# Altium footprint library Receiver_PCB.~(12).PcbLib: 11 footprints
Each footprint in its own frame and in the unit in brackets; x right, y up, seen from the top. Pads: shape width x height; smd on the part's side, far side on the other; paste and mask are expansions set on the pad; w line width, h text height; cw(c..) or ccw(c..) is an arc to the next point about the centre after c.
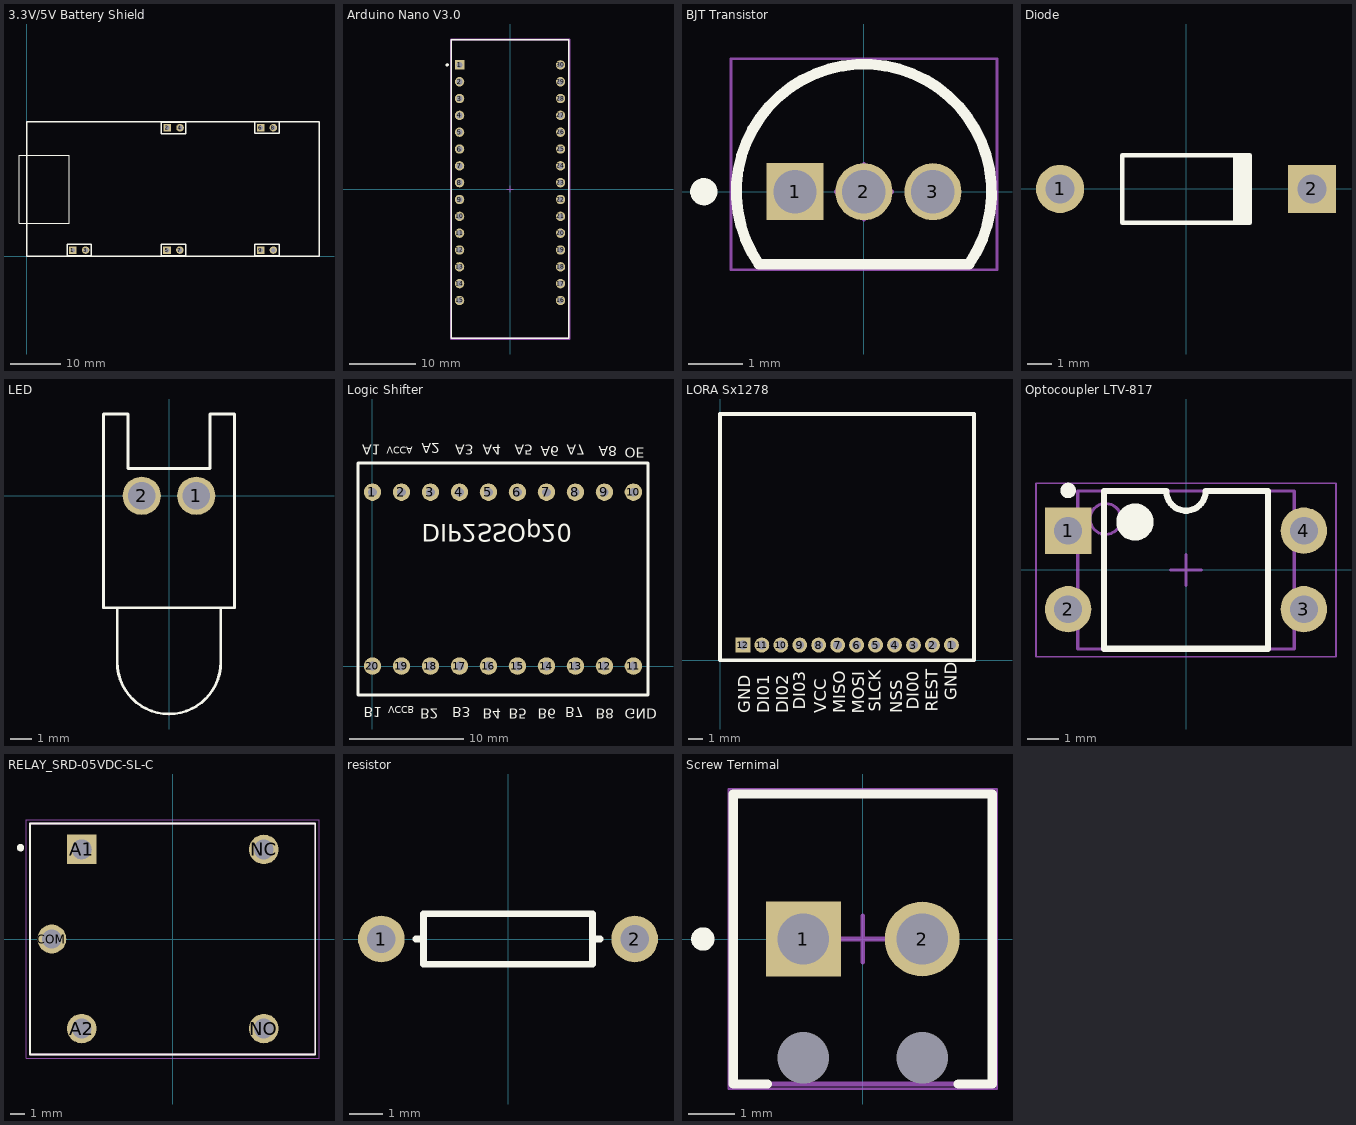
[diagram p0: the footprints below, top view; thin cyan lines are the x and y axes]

## 3.3V/5V Battery Shield [mm]
pads (10):
  rect 1.5x1.5 hole 0.9: 1(9.144,1.27) 2(27.853,25.518) 5(27.813,1.27) 6(46.355,25.527) 9(46.355,1.27)
  round 1.5 hole 0.9: 3(11.684,1.27) 4(30.393,25.518) 7(30.353,1.27) 8(48.895,25.527) 11(48.895,1.27)
Top Overlay:
  lines w0.127: -1.524,6.604 8.476,6.604 8.476,20.104 -1.524,20.104 -1.524,6.604
  lines w0.254: 0,0 57.935,0 57.935,26.753 0,26.753 0,0 ; 8.01,0.127 12.827,0.127 12.827,2.407 8.01,2.407 8.01,0.127 ; 26.679,0.127 31.496,0.127 31.496,2.407 26.679,2.407 26.679,0.127 ; 26.719,24.375 31.536,24.375 31.536,26.655 26.719,26.655 26.719,24.375 ; 45.221,0.127 50.038,0.127 50.038,2.407 45.221,2.407 45.221,0.127 ; 45.221,24.384 50.038,24.384 50.038,26.664 45.221,26.664 45.221,24.384

## Arduino Nano V3.0 [mil]
pads (30):
  rect 55.67x55.67 hole 35.98 paste-39370.1 mask+0: 1(-300,737.5)
  round 55.67 hole 35.98 paste-39370.1 mask+0: 2(-300,637.5) 3(-300,537.5) 4(-300,437.5) 5(-300,337.5) 6(-300,237.5) 7(-300,137.5) 8(-300,37.5) 9(-300,-62.5) 10(-300,-162.5) 11(-300,-262.5) 12(-300,-362.5) 13(-300,-462.5) 14(-300,-562.5) 15(-300,-662.5) 16(300,-662.5) 17(300,-562.5) 18(300,-462.5) 19(300,-362.5) 20(300,-262.5) 21(300,-162.5) 22(300,-62.5) 23(300,37.5) 24(300,137.5) 25(300,237.5) 26(300,337.5) 27(300,437.5) 28(300,537.5) 29(300,637.5) 30(300,737.5)
Top Overlay:
  circle w9.84: c-373.62,737.5 r4.92
  lines w7.87: -350,-887.5 -350,887.5 350,887.5 350,-887.5 -350,-887.5
Top 3D Body:
  lines w7.87: -350,-887.5 -350,887.5 350,887.5 350,-887.5 -350,-887.5
Top Courtyard:
  lines w7.87: -353.94,-891.44 -353.94,891.44 353.94,891.44 353.94,-891.44 -353.94,-891.44
Top Assembly:
  lines w7.87: -353.94,-891.44 -353.94,891.44 353.94,891.44 353.94,-891.44 -353.94,-891.44
Top Component Center:
  lines w3.94: -19.68,0 19.69,0 ; 0,-19.68 0,19.69
3D body "UNK_Arduino_A000005_eec.STEP": height 10, standoff 0, extent -353.94,-891.44 353.94,891.44

## BJT Transistor [mm]
pads (3):
  rect 1.05x1.05 hole 0.8: 1(-1.27,0)
  round 1.05 hole 0.8 paste+0: 2(0,0)
  round 1.05 hole 0.8: 3(1.27,0)
Top Overlay:
  circle w0.25: c-2.95,0 r0.125
  lines w0.2: -1.934,-1.335 cw(c0,0) 1.934,-1.335 -1.934,-1.335
Mechanical 13:
  lines w0.1: -1.934,-1.335 cw(c0,0) 1.934,-1.335 -1.934,-1.335
Mechanical 15:
  lines w0.05: -2.45,-1.435 2.45,-1.435 2.45,2.45 -2.45,2.45 -2.45,-1.435
  lines w0.1: -0.5,0 0.5,0 ; 0,-0.5 0,0.5
3D body: height 7.87, standoff 2.54, extent -2.349,-1.334 2.357,2.359

## Diode [mm]
pads (2):
  round 2 hole 1.2: 1(-5.23,0)
  rect 2x2 hole 1.2: 2(5.23,0)
Top Overlay:
  rectangle: 1.95,-1.401 2.75,1.399
  lines w0.2: 2.65,-1.4 -2.65,-1.4 -2.65,1.4 2.65,1.4

## LED [mil]
pads (2):
  round 70 hole 50: 1(50,0) 2(-50,0)
Top Overlay:
  lines w5: -95,-205 -95,-305 ccw(c0,-305) 95,-305 95,-205 ; -120,-205 -120,150 -75,150 -75,50 75,50 75,150 120,150 120,-205 -120,-205

## Logic Shifter [mil]
pads (20):
  round 60 hole 30: 1(0,600) 2(100,600) 3(200,600) 4(300,600) 5(400,600) 6(500,600) 7(600,600) 8(700,600) 9(800,600) 10(900,600) 11(900,0) 12(800,0) 13(700,0) 14(600,0) 15(500,0) 16(400,0) 17(300,0) 18(200,0) 19(100,0) 20(0,0)
Top Overlay:
  lines w10: -50,-100 950,-100 950,700 -50,700 -50,-100
  text "B1" at -30,-130 h60
  text "A8" at 780,770 h60
  text "A7" at 670,775 h60
  text "A6" at 580,770 h60
  text "A5" at 490,775 h60
  text "A4" at 380,775 h60
  text "A3" at 285,775 h60
  text "A2" at 170,780 h60
  text "A1" at -35,775 h60
  text "B3" at 275,-130.67 h60
  text "B4" at 380,-135 h60
  text "B5" at 470,-135.67 h60
  text "B6" at 570,-135.67 h60
  text "B7" at 665,-130 h60
  text "B8" at 770,-135.67 h60
  text "B2" at 165,-135 h60
  text "VCCA" at 50,765 h40
  text "OE" at 870,765 h60
  text "GND" at 870,-135.67 h60
  text "VCCB" at 55.04,-130.44 h40
  text "DIP2SSOp20" at 169.99,490 h60

## LORA Sx1278 [mm]
pads (12):
  round 1 hole 0.6: 1(15.494,1.016) 2(14.224,1.016) 3(12.954,1.016) 4(11.684,1.016) 5(10.414,1.016) 6(9.144,1.016) 7(7.874,1.016) 8(6.604,1.016) 9(5.334,1.016) 10(4.064,1.016) 11(2.794,1.016)
  rect 1x1 hole 0.6: 12(1.524,1.016)
Top Overlay:
  lines w0.254: 0,0 17,0 17,16.5 0,16.5 0,0
  text "GND" at 15.852,-2.664 h0.8
  text "REST" at 14.582,-3.463 h0.8
  text "DI00" at 13.312,-3.33 h0.8
  text "NSS" at 12.192,-3.556 h0.8
  text "SLCK" at 10.772,-3.463 h0.8
  text "MOSI" at 9.652,-3.601 h0.8
  text "MISO" at 8.382,-3.556 h0.8
  text "VCC" at 7.112,-3.556 h0.8
  text "DI03" at 5.692,-3.33 h0.8
  text "DI02" at 4.572,-3.556 h0.8
  text "GND" at 2.032,-3.556 h0.8
  text "DI01" at 3.302,-3.556 h0.8

## Optocoupler LTV-817 [mm]
pads (4):
  rect 1.5x1.5 hole 0.9: 1(-3.81,1.27)
  round 1.5 hole 0.9: 2(-3.81,-1.27) 3(3.81,-1.27) 4(3.81,1.27)
Top Overlay:
  circle w0.25: c-3.81,2.57 r0.125
  circle w0.6: c-1.65,1.55 r0.3
  lines w0.2: -2.65,-2.55 -2.65,2.55 -0.635,2.55 ccw(c0,2.55) 0.635,2.55 2.65,2.55 2.65,-2.55 -2.65,-2.55
Mechanical 13:
  circle w0.1: c-2.6,1.65 r0.5
  lines w0.1: -3.5,-2.55 -3.5,2.55 3.5,2.55 3.5,-2.55 -3.5,-2.55
Mechanical 15:
  lines w0.05: -4.85,-2.8 -4.85,2.8 4.85,2.8 4.85,-2.8 -4.85,-2.8
  lines w0.1: -0.5,0 0.5,0 ; 0,-0.5 0,0.5
3D body: height 2.37, standoff 0, extent -3.945,0.77 -3.675,1.77
3D body: height 2.64, standoff 2.37, extent -3.945,0.77 -3.5,1.77
3D body: height 0, standoff -1.6, extent -3.945,0.91 -3.675,1.63
3D body: height 2.37, standoff 0, extent -3.945,-1.77 -3.675,-0.77
3D body: height 2.64, standoff 2.37, extent -3.945,-1.77 -3.5,-0.77
3D body: height 0, standoff -1.6, extent -3.945,-1.63 -3.675,-0.91
3D body: height 2.37, standoff 0, extent 3.675,-1.77 3.945,-0.77
3D body: height 2.64, standoff 2.37, extent 3.5,-1.77 3.945,-0.77
3D body: height 0, standoff -1.6, extent 3.675,-1.63 3.945,-0.91
3D body: height 2.37, standoff 0, extent 3.675,0.77 3.945,1.77
3D body: height 2.64, standoff 2.37, extent 3.5,0.77 3.945,1.77
3D body: height 0, standoff -1.6, extent 3.675,0.91 3.945,1.63
3D body: height 4.5, standoff 0.5, extent -3.5,-2.55 3.5,2.55

## RELAY_SRD-05VDC-SL-C [mm]
pads (5):
  rect 1.98x1.98 hole 1.32 paste+0: A1(-6.1,6)
  round 1.98 hole 1.32: A2(-6.1,-6) NC(6.1,6) NO(6.1,-6)
  round 1.935 hole 1.29: COM(-8.1,0)
Top Overlay:
  circle w0.3: c-10.2,6.119 r0.1
  lines w0.127: -9.55,-7.75 9.55,-7.75 9.55,7.75 -9.55,7.75 -9.55,-7.75
Mechanical 13:
  lines w0.127: -9.55,-7.75 9.55,-7.75 9.55,7.75 -9.55,7.75 -9.55,-7.75
Mechanical 15:
  lines w0.05: -9.8,-8 9.8,-8 9.8,8 -9.8,8 -9.8,-8
3D body "step_temp.STEP": height 15.8, standoff -3, extent -9.6,-7.8 9.6,7.8

## resistor [mm]
pads (2):
  round 1.4 hole 0.85: 1(-3.81,0) 2(3.81,0)
Top Overlay:
  lines w0.2: -2.769,0 -2.54,0 ; 2.769,0 2.54,0 ; 2.54,0 2.54,0.762 -2.54,0.762 -2.54,-0.762 2.54,-0.762 2.54,0

## Screw Ternimal [mm]
pads (4):
  rect 1.6x1.6 hole 1.1: 1(-1.27,0)
  round 1.6 hole 1.1: 2(1.27,0)
  round 0 hole 1.1 unplated: MH1(-1.27,-2.54) MH2(1.27,-2.54)
Top Overlay:
  circle w0.25: c-3.42,0 r0.125
  lines w0.2: -2.038,-3.1 -2.77,-3.1 -2.77,3.1 2.77,3.1 2.77,-3.1 2.038,-3.1
Mechanical 13:
  lines w0.1: -2.77,-3.1 2.77,-3.1 2.77,3.1 -2.77,3.1 -2.77,-3.1
Mechanical 15:
  lines w0.05: -2.87,-3.2 -2.87,3.2 2.87,3.2 2.87,-3.2 -2.87,-3.2
  lines w0.1: -0.5,0 0.5,0 ; 0,-0.5 0,0.5
3D body "1725656.stp": height 9, standoff -3, extent -2.77,-3.1 2.77,3.1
